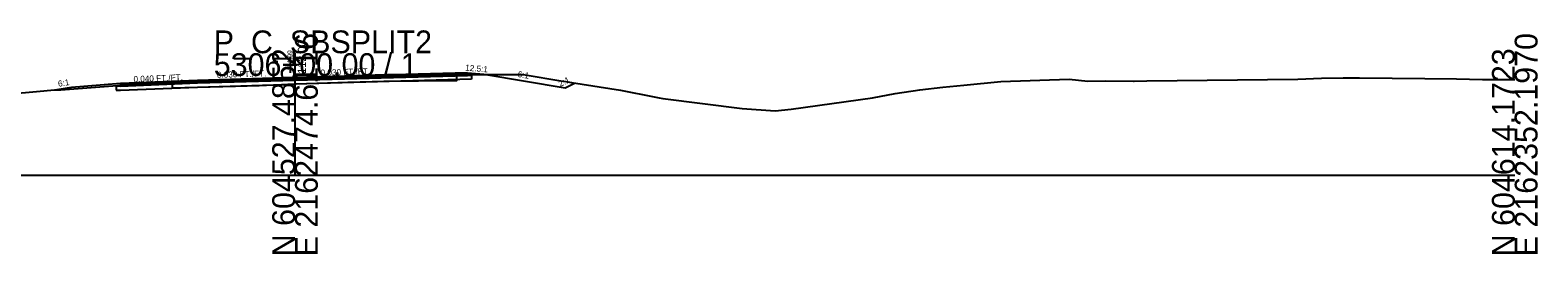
# Model space of a CAD drawing. Extents: x -26 to 1303, y -10 to 12033.
# Drawn here: x 1117.4 to 1302.8, y 990.3 to 1017.8 of the extents above; entities that cross this region are included whole.
import ezdxf

# ---------------------------------------------------------------- set-up
doc = ezdxf.new("R2010")
doc.units = 0
for name, color, linetype in [('RD_GPK_XS_Cell', 7, 'Continuous'), ('RD_XS_Base', 7, 'Continuous'), ('RD_XS_ExGround', 7, 'Continuous'), ('RD_XS_ExPaveRet', 7, 'Continuous'), ('RD_XS_Greenside', 7, 'Continuous'), ('RD_XS_Pave', 7, 'Continuous'), ('RD_XS_PaveOvlay_CP', 7, 'Continuous'), ('RD_XS_TieSlope', 7, 'Continuous'), ('RD_XS_TX_Elev_EX', 7, 'Continuous'), ('RD_XS_TX_Elev_PR', 7, 'Continuous'), ('RD_XS_TX_ShdSlope', 7, 'Continuous'), ('RD_XS_TX_Slope', 7, 'Continuous')]:
    doc.layers.add(name, color=color, linetype=linetype)

msp = doc.modelspace()

# ---------------------------------------------------------------- linework, layer by layer
at = {"layer": 'RD_GPK_XS_Cell'}
for p, q in [((1150, 1000), (1150, 1015)), ((1000, 1000), (1150, 1000)), ((1150, 1000), (1300, 1000))]:
    msp.add_line(p, q, dxfattribs=at)
at = {"layer": 'RD_XS_Base'}
for p, q in [((1128.52, 1010.96), (1128.02, 1010.94)), ((1128.02, 1010.94), (1128.02, 1010.94)), ((1128.02, 1010.94), (1128.02, 1010.44)), ((1138, 1011.34), (1128.52, 1010.96)), ((1128.52, 1010.96), (1128.52, 1010.96)), ((1128.52, 1010.46), (1138, 1010.84)), ((1150, 1011.68), (1138, 1011.34)), ((1138, 1011.34), (1138, 1011.34)), ((1138, 1010.84), (1150, 1011.18)), ((1138, 1010.84), (1138, 1010.84)), ((1150, 1011.68), (1171.21, 1012.27)), ((1150, 1011.18), (1150, 1011.84)), ((1150, 1011.84), (1150, 1011.84)), ((1150, 1011.84), (1150, 1011.84)), ((1150, 1011.84), (1150, 1011.68)), ((1171.71, 1011.79), (1150, 1011.18)), ((1150, 1011.68), (1150, 1011.68)), ((1150, 1011.18), (1150, 1011.68)), ((1150, 1011.68), (1150, 1011.68)), ((1150, 1011.68), (1150, 1011.68)), ((1150, 1011.18), (1150, 1011.18)), ((1162, 1012.01), (1162, 1012.01)), ((1162, 1012.01), (1162, 1012.01)), ((1162, 1011.51), (1162, 1011.51)), ((1162, 1011.51), (1162, 1011.51)), ((1171.21, 1012.27), (1171.21, 1012.27)), ((1171.71, 1012.29), (1171.71, 1011.79)), ((1171.71, 1012.25), (1171.71, 1012.25)), ((1128.02, 1010.44), (1128.52, 1010.46)), ((1128.52, 1010.46), (1128.52, 1010.46))]:
    msp.add_line(p, q, dxfattribs=at)
at = {"layer": 'RD_XS_ExGround'}
msp.add_lwpolyline([(1109.48, 1009.5), (1118.19, 1010.3), (1120.42, 1010.5), (1121.18, 1010.5), (1128.11, 1011.02), (1134.9, 1011.49), (1142.7, 1011.69), (1145.57, 1011.78), (1150.12, 1012), (1156.55, 1012.19), (1160.97, 1012.33), (1169.41, 1012.38), (1169.91, 1012.38), (1170.3, 1012.38), (1178.05, 1012.38), (1182.94, 1011.56), (1183.29, 1011.5), (1184.01, 1011.39), (1190.01, 1010.46), (1194.17, 1009.62), (1194.79, 1009.49), (1195.23, 1009.43), (1204.99, 1008.2), (1209.04, 1007.9), (1211.03, 1008.13), (1221.02, 1009.5), (1223.8, 1010.03), (1226.83, 1010.5), (1229.65, 1010.81), (1232.24, 1011.06), (1236.79, 1011.5), (1245.2, 1011.82), (1247.49, 1011.57), (1249.61, 1011.59), (1253.12, 1011.58), (1253.21, 1011.58), (1254.74, 1011.6), (1273.32, 1011.82), (1276.23, 1011.91), (1278.88, 1011.97), (1280.92, 1011.96), (1288.95, 1011.87), (1292.83, 1011.83), (1296.04, 1011.78), (1299.32, 1011.77), (1300, 1011.76)], dxfattribs=at)
at = {"layer": 'RD_XS_ExPaveRet'}
for points in [[(1169.41, 1012.38), (1160.97, 1012.33), (1160.97, 1012.33), (1160.97, 1012.33), (1156.55, 1012.19), (1156.55, 1012.19), (1150.12, 1012), (1150.12, 1012), (1145.57, 1011.78), (1142.7, 1011.69), (1142.7, 1011.69), (1134.9, 1011.49), (1134.9, 1011.49), (1134.9, 1011.49), (1134.9, 1010.74), (1134.9, 1010.74), (1142.7, 1010.94), (1142.7, 1010.94), (1145.57, 1011.03), (1150.12, 1011.25), (1150.12, 1011.25), (1156.55, 1011.44), (1156.55, 1011.44), (1160.97, 1011.58), (1160.97, 1011.58), (1160.97, 1011.58), (1169.41, 1011.63), (1169.41, 1011.63), (1169.91, 1011.63), (1169.91, 1012.38), (1169.91, 1012.38), (1169.41, 1012.38), (1169.41, 1012.38)], [(1169.41, 1012.38), (1160.97, 1012.33), (1156.55, 1012.19), (1150.12, 1012), (1145.57, 1011.78), (1142.7, 1011.69), (1134.9, 1011.49), (1134.9, 1010.74), (1142.7, 1010.94), (1145.57, 1011.03), (1150.12, 1011.25), (1156.55, 1011.44), (1160.97, 1011.58), (1169.41, 1011.63), (1169.91, 1011.63), (1169.91, 1012.38), (1169.41, 1012.38)]]:
    msp.add_lwpolyline(points, dxfattribs=at)
at = {"layer": 'RD_XS_Greenside'}
for p, q in [((1173.21, 1012.43), (1183.21, 1010.76)), ((1122.52, 1010.8), (1120.71, 1010.5)), ((1183.21, 1010.76), (1184.35, 1011.33))]:
    msp.add_line(p, q, dxfattribs=at)
at = {"layer": 'RD_XS_Pave'}
for p, q in [((1171.21, 1012.59), (1150, 1012)), ((1171.21, 1012.43), (1150, 1011.84)), ((1150, 1011.84), (1171.21, 1012.43)), ((1171.21, 1012.43), (1171.21, 1012.59)), ((1171.21, 1012.59), (1171.21, 1012.59)), ((1171.21, 1012.27), (1171.21, 1012.43)), ((1171.21, 1012.43), (1171.21, 1012.43)), ((1138, 1011.66), (1128.52, 1011.28)), ((1128.52, 1011.12), (1138, 1011.5)), ((1138, 1011.5), (1128.52, 1011.12)), ((1128.52, 1010.96), (1138, 1011.34)), ((1128.52, 1011.28), (1128.52, 1011.28)), ((1128.52, 1011.28), (1128.52, 1011.12)), ((1128.52, 1011.12), (1128.52, 1011.12)), ((1128.52, 1011.12), (1128.52, 1010.96)), ((1150, 1012), (1138, 1011.66)), ((1138, 1011.5), (1150, 1011.84)), ((1150, 1011.84), (1138, 1011.5)), ((1138, 1011.34), (1150, 1011.68)), ((1138, 1011.66), (1138, 1011.66)), ((1138, 1011.5), (1138, 1011.5)), ((1138, 1011.5), (1138, 1011.5)), ((1138, 1011.34), (1138, 1011.34)), ((1150, 1011.68), (1171.71, 1012.29)), ((1150, 1012), (1150, 1012)), ((1150, 1011.84), (1150, 1011.84)), ((1150, 1011.84), (1150, 1011.84)), ((1150, 1011.84), (1150, 1011.68)), ((1150, 1011.84), (1150, 1011.84)), ((1150, 1011.68), (1150, 1011.84)), ((1150, 1011.84), (1150, 1011.84)), ((1150, 1011.84), (1150, 1011.84)), ((1150, 1011.68), (1150, 1011.68)), ((1150, 1011.68), (1150, 1011.68)), ((1162, 1012.33), (1162, 1012.33)), ((1162, 1012.33), (1162, 1012.33)), ((1162, 1012.17), (1162, 1012.17)), ((1162, 1012.17), (1162, 1012.17)), ((1162, 1012.17), (1162, 1012.17)), ((1162, 1012.17), (1162, 1012.17)), ((1162, 1012.01), (1162, 1012.01)), ((1162, 1012.01), (1162, 1012.01))]:
    msp.add_line(p, q, dxfattribs=at)
at = {"layer": 'RD_XS_PaveOvlay_CP'}
for p, q in [((1171.21, 1012.59), (1150, 1012)), ((1138, 1011.66), (1128.52, 1011.28)), ((1150, 1012), (1138, 1011.66)), ((1138, 1011.66), (1138, 1011.66)), ((1150, 1012), (1150, 1012)), ((1162, 1012.33), (1162, 1012.33)), ((1162, 1012.33), (1162, 1012.33))]:
    msp.add_line(p, q, dxfattribs=at)
at = {"layer": 'RD_XS_TieSlope'}
for p, q in [((1171.21, 1012.59), (1173.21, 1012.43)), ((1128.52, 1011.28), (1122.52, 1010.8))]:
    msp.add_line(p, q, dxfattribs=at)

# ---------------------------------------------------------------- texts
at = {"layer": 'RD_GPK_XS_Cell'}
for s, p in [('P_C_SBSPLIT2', (1140, 1015)), ('5306+00.00 / 1', (1140, 1012.2))]:
    msp.add_text(s, height=2.8, dxfattribs=at).set_placement(p)
for s, p in [('E 2162474.6116', (1152.8, 990)), ('E 2162352.1970', (1302.8, 990)), ('N 604527.4852', (1150, 990)), ('N 604614.1723', (1300, 990))]:
    msp.add_text(s, height=2.8, rotation=90, dxfattribs=at).set_placement(p)
at = {"layer": 'RD_XS_TX_Elev_EX'}
msp.add_text('111.99', height=0.6, rotation=90, dxfattribs=at).set_placement((1149.67, 1012.84))
at = {"layer": 'RD_XS_TX_Elev_PR'}
msp.add_text('112.00', height=1, rotation=90, dxfattribs=at).set_placement((1151.34, 1012.47))
at = {"layer": 'RD_XS_TX_ShdSlope'}
msp.add_text('12.5:1', height=0.75, rotation=355.4261, dxfattribs=at).set_placement((1170.91, 1012.86))
at = {"layer": 'RD_XS_TX_Slope'}
for s, rotation, p in [('0.040 FT./FT.', 2.2906, (1130.15, 1011.43)), ('0.030 FT./FT.', 1.7184, (1140.41, 1011.96)), ('0.030 FT./FT.', 1.7184, (1153.16, 1012.23)), ('6:1', 350.5358, (1177.34, 1012.08)), ('6:1', 350.5358, (1177.34, 1012.08)), ('6:1', 9.4623, (1120.92, 1010.86)), ('2:1', 26.5651, (1182.63, 1010.85))]:
    msp.add_text(s, height=0.75, rotation=rotation, dxfattribs=at).set_placement(p)

doc.saveas('drawing.dxf')
